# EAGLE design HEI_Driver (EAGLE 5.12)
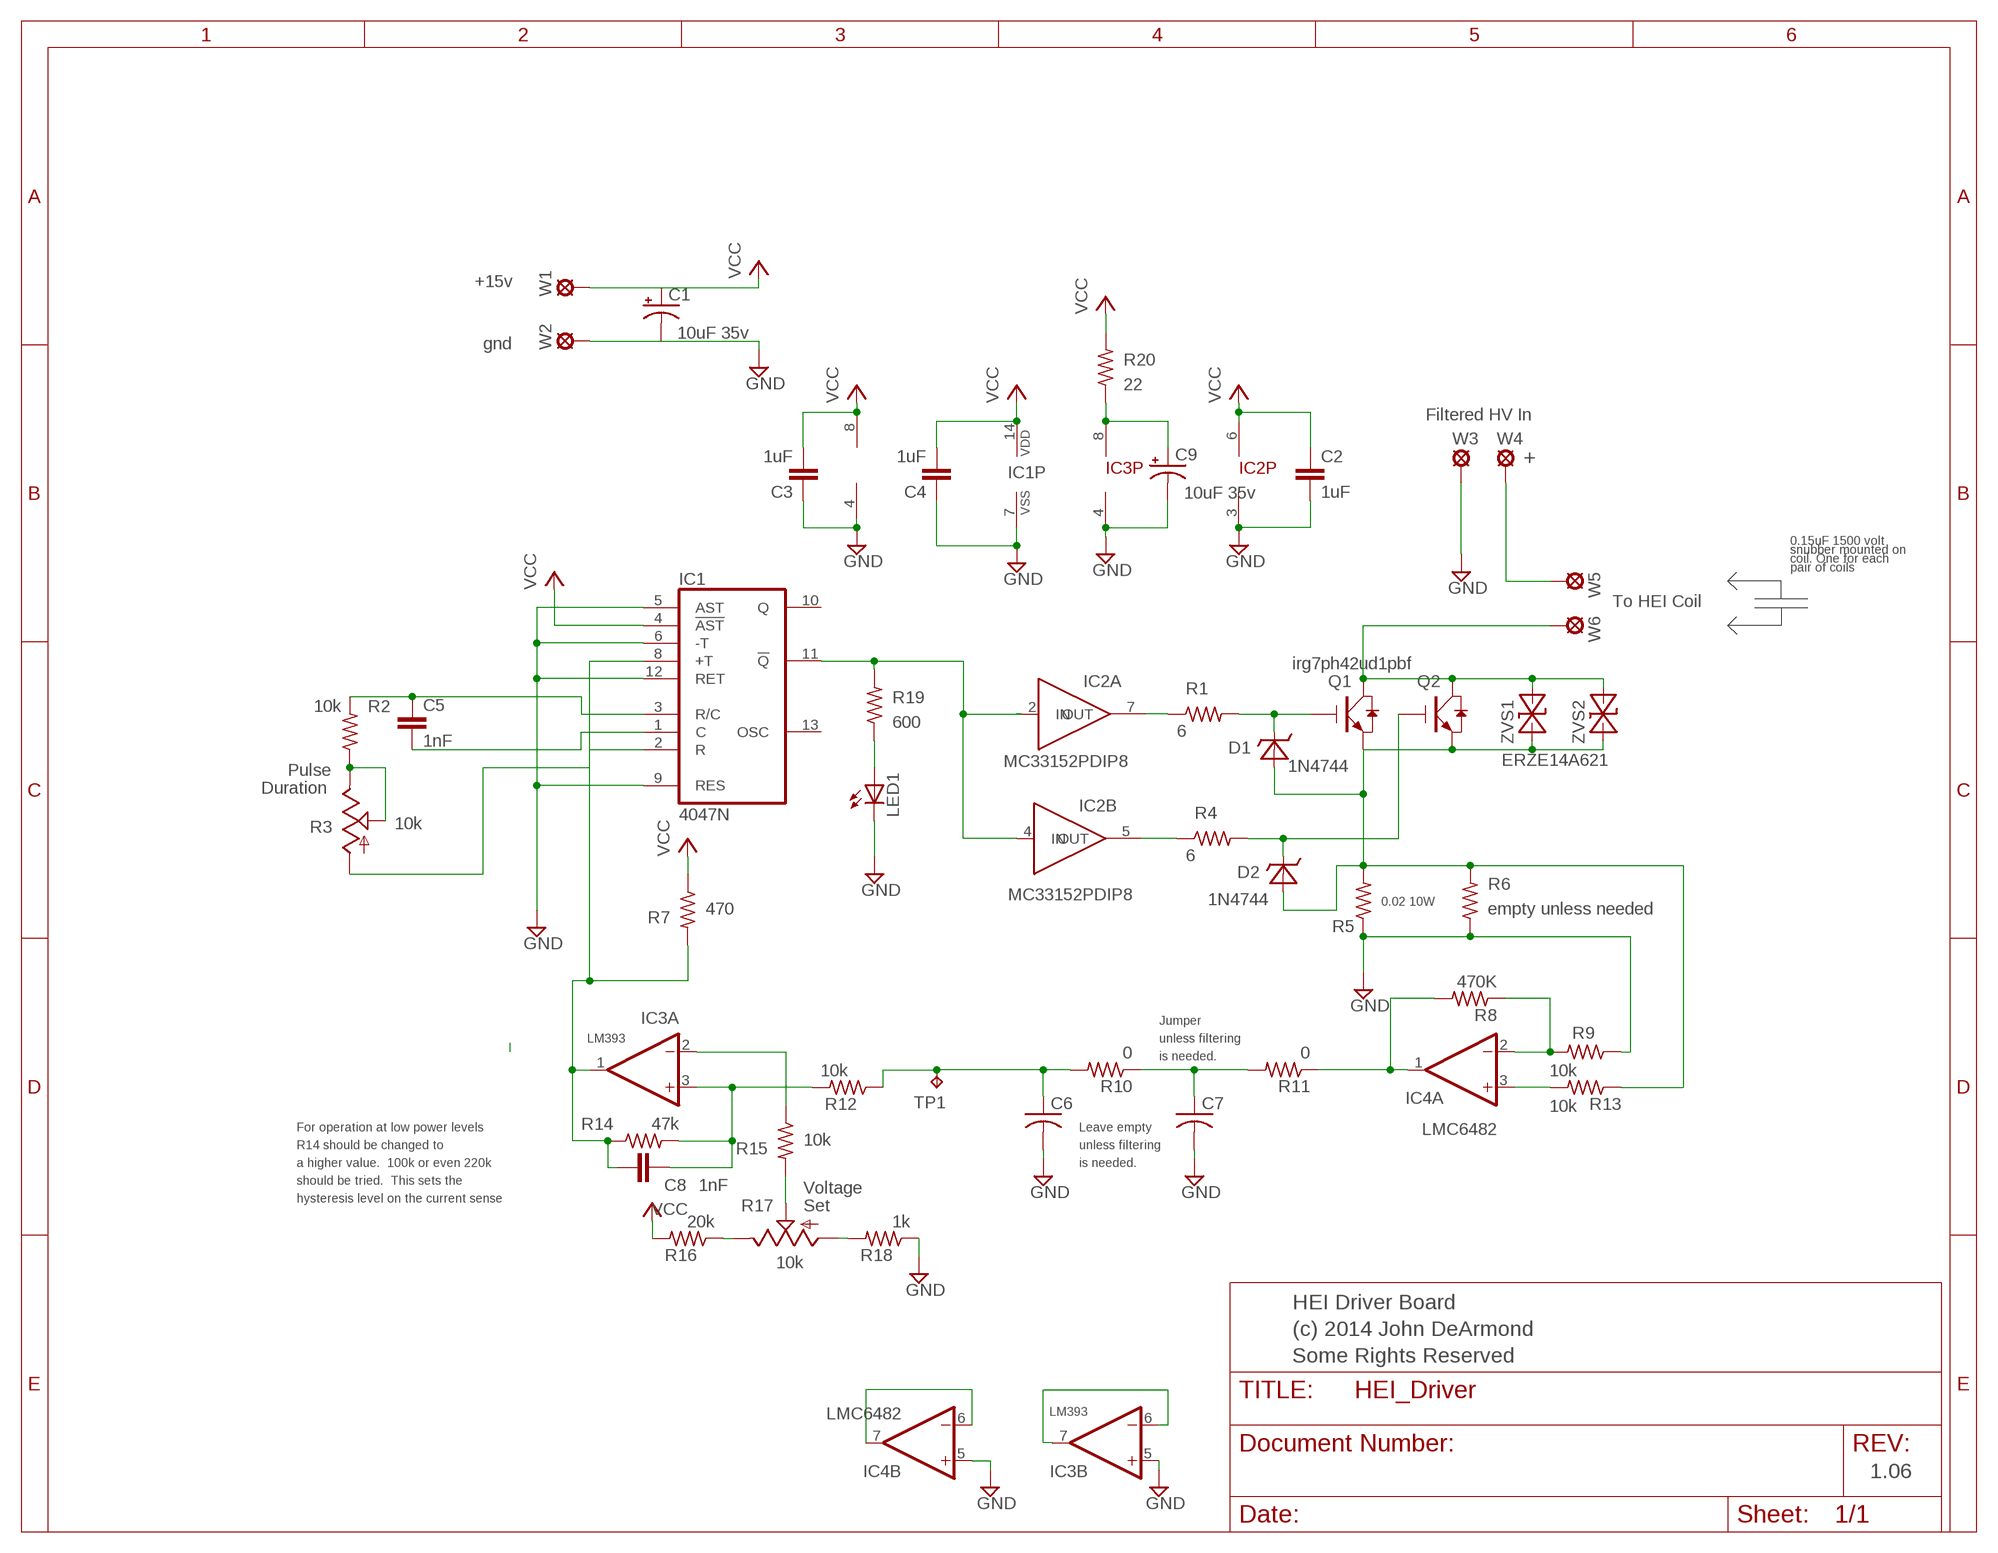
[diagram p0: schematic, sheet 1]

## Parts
C1  10uF 35v  CPOL-USE2.5-6  [E2,5-6]
C2  1uF  C5/5.5  [C5B5.5]
C3  1uF  C5/5.5  [C5B5.5]
C4  1uF  C5/5.5  [C5B5.5]
C5  1nF  C5/5.5  [C5B5.5]
C6  100p  C-US050-030X075  [C050-030X075]
C7  100p  C-US050-030X075  [C050-030X075]
C8  1nF  C5/5.5  [C5B5.5]
C9  10uF 35v  CPOL-USE2.5-6  [E2,5-6]
D1  1N4744  [DO41-10]
D2  1N4744  [DO41-10]
IC1  4047N  [DIL14]
IC2  MC33152PDIP8  [DIL08]
IC3  LM393  2AMP_P8+4N  [DIL08]
IC4  LMC6482  2AMP_P8+4D  [SO08]
LED1  LED_5MM_ROUND5MM_ROUND  [LED_5MM_ROUND]
Q1  irg7ph42udpbf  IGBT_DIODE  [TO247BV]
Q2  irg7ph42ud1pbf  IGBT_DIODE  [TO247BV]
R1  6  R-US_0207/10  [0207/10]
R2  10k  R-US_0207/10  [0207/10]
R3  10k  TRIM_US-  [3_TENTH_INCH_PADS]
R4  6  R-US_0207/10  [0207/10]
R5  0.02 10W  R-US_0613/15  [P0613/15-0.065_DRILL]
R6  empty unless needed  R-US_0613/15  [P0613/15-0.065_DRILL]
R7  470  R-US_0207/10  [0207/10]
R8  470K  R-US_0207/10  [0207/10]
R9  10k  R-US_0207/10  [0207/10]
R10  0  R-US_0207/10  [0207/10]
R11  0  R-US_0207/10  [0207/10]
R12  10k  R-US_0207/10  [0207/10]
R13  10k  R-US_0207/10  [0207/10]
R14  47k  R-US_0207/10  [0207/10]
R15  10k  R-US_0207/10  [0207/10]
R16  20k  R-US_0207/10  [0207/10]
R17  10k  TRIM_US-  [3_TENTH_INCH_PADS]
R18  1k  R-US_0207/10  [0207/10]
R19  600  R-US_0207/10  [0207/10]
R20  22  R-US_0207/10  [0207/10]
TP1  TPPAD1-17  [P1-17]
W1  PAD_25  [PAD_2.5MM]
W2  PAD_25  [PAD_2.5MM]
W3  PAD_25  [PAD_2.5MM]
W4  PAD_25  [PAD_2.5MM]
W5  PAD_25  [PAD_2.5MM]
W6  PAD_25  [PAD_2.5MM]
ZVS1  ERZE14A621  TVSTVS_0.45  [TVS_0.45]
ZVS2  ZNR14621  TVSTVS_0.45  [TVS_0.45]

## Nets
CURRENT_SENSE_+: D1.A D2.A Q1.S(E) Q2.S(E) R5.2 R6.2 R13.1 ZVS1.P$1(A1) ZVS2.P$1(A1)
GND: C1.- C2.2 C3.1 C4.1 C6.2 C7.2 C9.- IC1.5(AST) IC1.6(-T) IC1.7(VSS) IC1.9(RES) IC1.12(RET) IC2.3(P:-PWR) IC3.4(P:-PWR) IC3.5(B:+IN) IC4.4(P:V-) IC4.5(B:+IN) LED1.P$2(C) R5.1 R6.1 R9.1 R18.1 W2.W$1(MP) W3.W$1(MP)
MAIN_CURRENT: C6.1 R10.2 R12.1 TP1.TP
N$1: D1.C Q1.G R1.2
N$2: IC2.7(A:OUT) R1.1
N$3 [High Voltage]: Q1.D(C) Q2.D(C) W6.W$1(MP)
N$4: IC4.3(A:+IN) R13.2
N$5 [High Voltage]: W4.W$1(MP) W5.W$1(MP)
N$6: IC1.11(!Q) IC2.2(A:IN) IC2.4(B:IN) R19.2
N$7: IC2.5(B:OUT) R4.1
N$8: IC3.6(B:-IN) IC3.7(B:OUT)
N$9: C8.2 IC3.3(A:+IN) R12.2 R14.2
N$10: IC4.2(A:-IN) R8.1 R9.2
N$11: R15.2 R17.2(S)
N$12: C5.1 IC1.3(R/C) R2.2
N$14: C8.1 IC1.8(+T) IC3.1(A:OUT) R7.2 R14.1
N$15: R16.1 R17.3(E)
N$16: R17.1(A) R18.2
N$17: C5.2 IC1.1(C)
N$18: IC1.2(R) R3.1(A)
N$19: R2.1 R3.2(S) R3.3(E)
N$20: IC3.2(A:-IN) R15.1
N$21: IC4.1(A:OUT) R8.2 R11.1
N$22: D2.C Q2.G R4.2
N$23: LED1.P$1(A) R19.1
N$24: C9.+ IC3.8(P:PWR) R20.1
N$55: C7.1 R10.1 R11.2
N$66: IC4.6(B:-IN) IC4.7(B:OUT)
VCC: C1.+ C2.1 C3.2 C4.2 IC1.4(!AST) IC1.14(VDD) IC2.6(P:PWR) IC4.8(P:V+) R7.1 R16.2 R20.2 W1.W$1(MP)
Unconnected: IC1.10(Q) IC1.13(OSC) ZVS1.P$2(A2) ZVS2.P$2(A2)

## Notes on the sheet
- +15v
- gnd
- Filtered HV In
- +
- 0.15uF 1500 volt
- snubber mounted on
- coil. One for each
- pair of coils
- To HEI Coil
- Pulse
- Duration
- Jumper
- unless filtering
- is needed.
- For operation at low power levels | Leave empty
- R14 should be changed to | unless filtering
- a higher value.  100k or even 220k | is needed.
- should be tried.  This sets the
- Voltage
- hysteresis level on the current sense
- Set
- HEI Driver Board
- (c) 2014 John DeArmond
- Some Rights Reserved
- 1.06

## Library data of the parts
C1 C9 = rcl:CPOL-US: POLARIZED CAPACITOR, American symbol
C2-C5 C8 = capacitor-wima:C: CAPACITOR
C6 C7 = 00John:C-US: CAPACITOR, American symbol
D1 D2 = 00John:1N4744: 1N4744 15 volt 1 watt Zener Diode
IC1 = 00John:4047: LP monostable/astable MULTIVIBRATOR
IC2 = 00John:MC33152: MC33152 High Speed Dual non-Inverting Mosfet Gate Driver. 1.5 amp Totem Pole output
IC3 = 00John:2AMP_P8+4: OP AMP
IC4 = linear:2AMP_P8+4: OP AMP
LED1 = 00John:LED_5MM_ROUND: LED, Single
Q1 Q2 = 00John:IGBT_DIODE: IGBT with reverse diode
R1 R4-R6 R8-R11 R13 R19 R20 = 00John:R-US_: RESISTOR, American symbol
R2 R7 R12 R14-R16 R18 = rcl:R-US_: RESISTOR, American symbol
R3 R17 = 00John:TRIM_US-: POTENTIOMETER
TP1 = testpad:TP: Test pad
W1-W6 = 00John:PAD_25: Wire Pad
ZVS1 ZVS2 = 00John:TVS: Transient Voltage Suppressor

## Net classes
1 High Voltage: clearance 1.016 mm

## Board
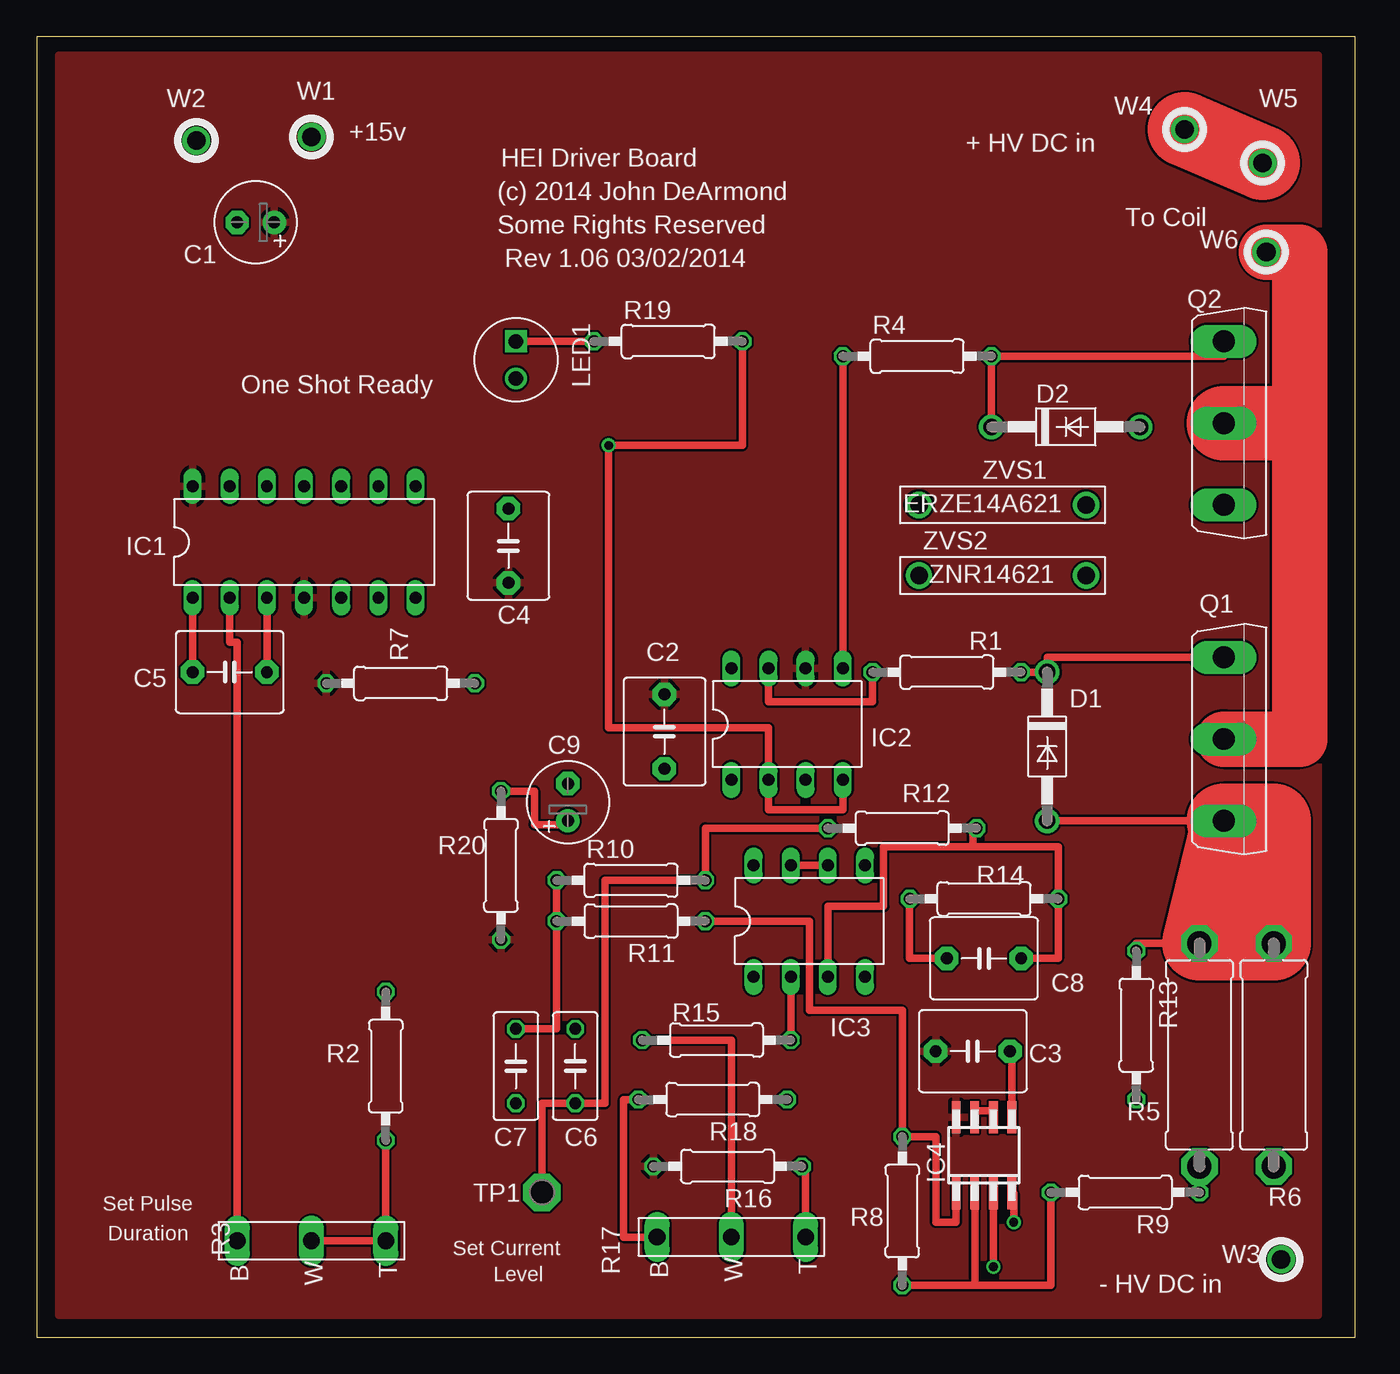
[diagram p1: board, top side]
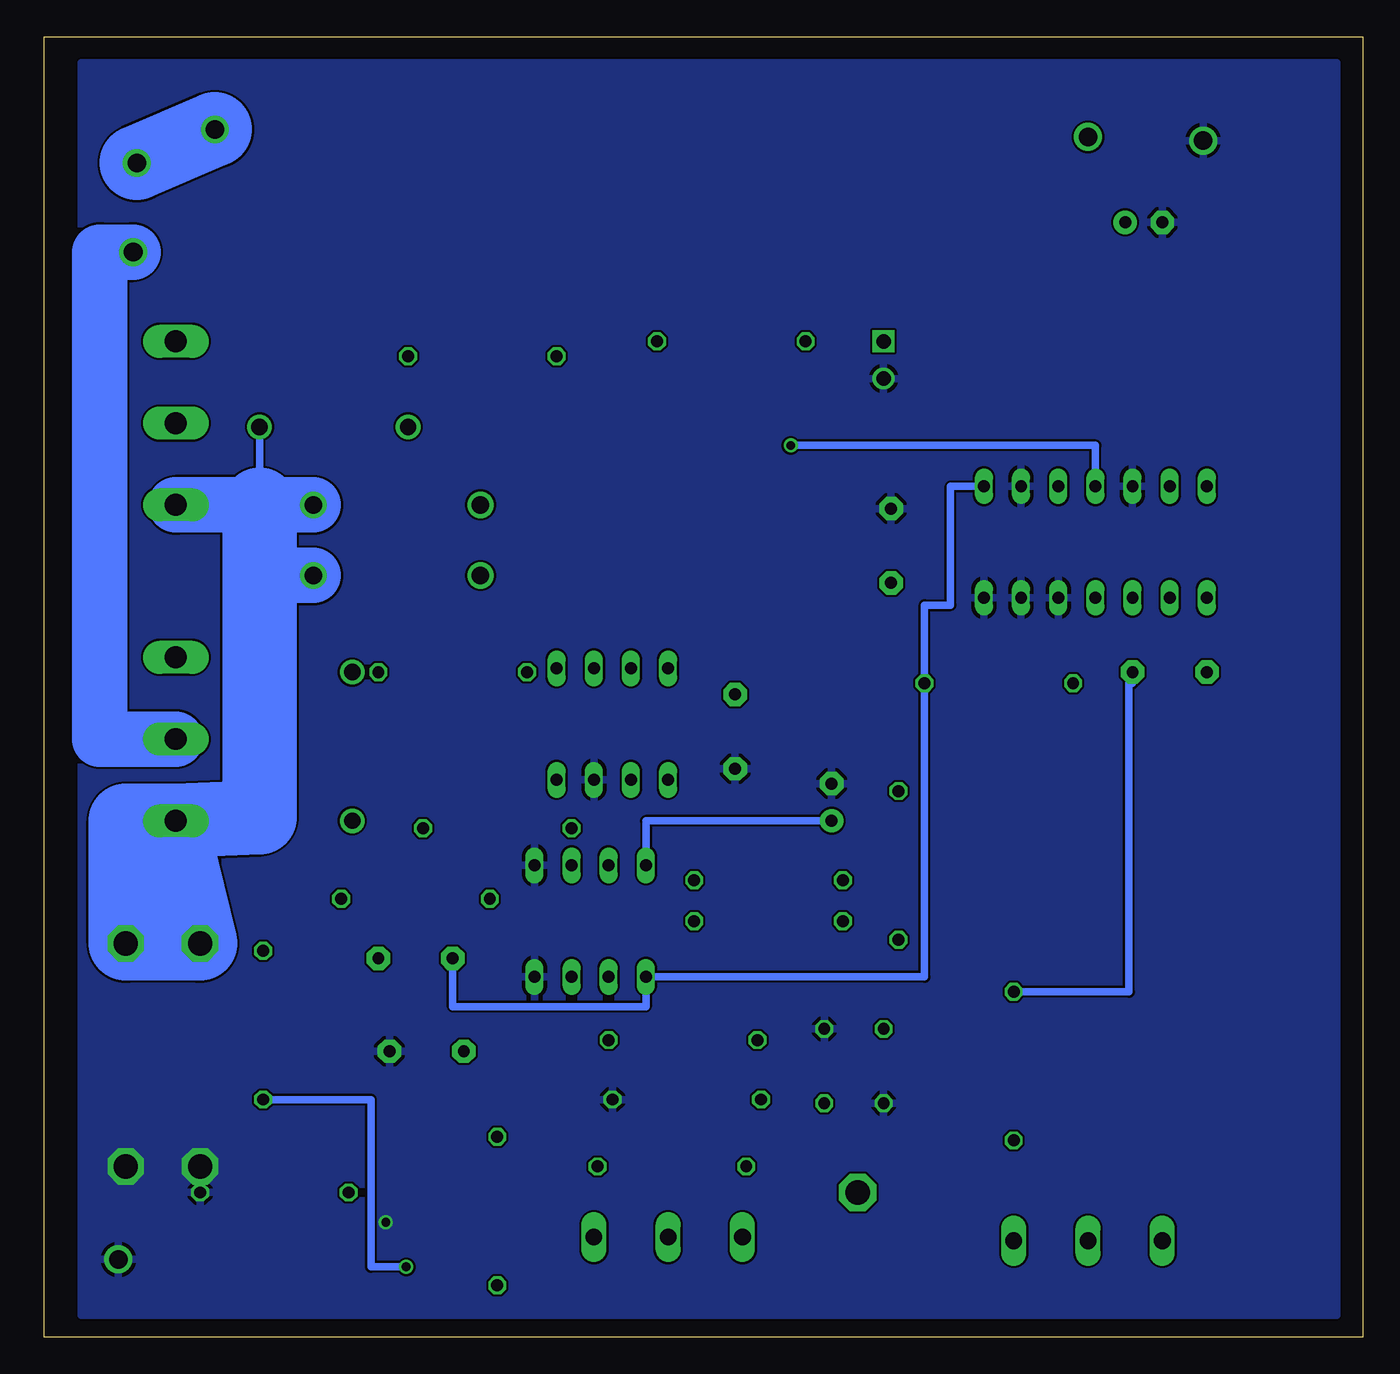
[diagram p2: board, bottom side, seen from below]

Size 90.17 x 88.9 mm. Coordinates in mm from the lower left corner, seen from the top.
Outline: 0,0 90.17,0 90.17,88.9 0,88.9 0,0
Copper layers (1*16): Top 0.0356mm / dielectric 1.5011mm / Bottom 0.0356mm
Design rules "OSH_Park_LaenPCBOrder": minimum track width 6mil, minimum drill 13mil, track to track 6mil, track to pad 6mil, pad to pad 6mil, via to via 6mil, smd to smd 6mil, copper to edge 15mil, drill to drill 6mil, minimum pad ring 7mil, minimum via ring 7mil, stop-mask expansion 3mil, vias tented up to drill 0mil, thermal gap 10mil

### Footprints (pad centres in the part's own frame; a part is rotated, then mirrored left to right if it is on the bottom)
E2,5-6 = drill 0.813 pad 1.6 round: + -1.27,0 | drill 0.813 pad 1.6 octagon: - 1.27,0
C5B5.5 = drill 0.813 pad 1.6 octagon: 1 -2.54,0; 2 2.54,0
C050-030X075 = drill 0.813 octagon: 1 -2.54,0; 2 2.54,0
DO41-10 = drill 1.118 round: A 5.08,0; C -5.08,0
DIL14 = drill 0.813 long: 1 -7.62,-3.81; 2 -5.08,-3.81; 3 -2.54,-3.81; 4 0,-3.81; 5 2.54,-3.81; 6 5.08,-3.81; 7 7.62,-3.81; 8 7.62,3.81; 9 5.08,3.81; 10 2.54,3.81; 11 0,3.81; 12 -2.54,3.81; 13 -5.08,3.81; 14 -7.62,3.81
DIL08 = drill 0.813 long: 1 -3.81,-3.81; 2 -1.27,-3.81; 3 1.27,-3.81; 4 3.81,-3.81; 5 3.81,3.81; 6 1.27,3.81; 7 -1.27,3.81; 8 -3.81,3.81
SO08 = smd 0.6 x 2.2: 1 -1.905,-2.6; 2 -0.635,-2.6; 3 0.635,-2.6; 4 1.905,-2.6; 5 1.905,2.6; 6 0.635,2.6; 7 -0.635,2.6; 8 -1.905,2.6
LED_5MM_ROUND = drill 1 square: P$1 0,0 | drill 1 round: P$2 2.54,0
TO247BV = drill 1.499 long: D 0,-2.921; G -5.588,-2.921; S 5.588,-2.921
0207/10 = drill 0.813 octagon: 1 -5.08,0; 2 5.08,0
3_TENTH_INCH_PADS = drill 1.143 long: 1 0,5.08; 2 0,0; 3 0,-5.08
P0613/15-0.065_DRILL = drill 1.651 octagon: 1 -7.62,0; 2 7.62,0
P1-17 = drill 1.702 pad 2.54 octagon: TP 0,0
PAD_2.5MM = drill 1.27 round: W$1 0,0
TVS_0.45 = drill 1.2 round: P$1 -5.715,0; P$2 5.715,0

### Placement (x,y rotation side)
C1  14.99,76.2 180 top
C2  42.93,41.4 270 top
C3  64.01,19.56 180 top
C4  32.26,54.1 270 top
C5  13.21,45.47 180 top
C6  36.83,18.54 90 top
C7  32.77,18.54 270 top
C8  64.77,25.91 0 top
C9  36.32,36.58 90 top
D1  69.09,40.39 270 top
D2  70.36,62.23 0 top
IC1  18.29,54.36 0 top
IC2  51.31,41.91 0 top
IC3  52.83,28.45 0 top
IC4  64.77,12.45 0 top
LED1  32.77,68.07 270 top
Q1  84.07,40.89 270 top
Q2  84.07,62.48 270 top
R1  62.23,45.47 0 top
R2  23.88,18.54 90 top
R3  18.8,6.6 90 top
R4  60.2,67.06 0 top
R5  79.5,19.3 90 top
R6  84.58,19.3 90 top
R7  24.89,44.7 0 top
R8  59.18,8.64 90 top
R9  74.42,9.91 180 top
R10  40.64,31.24 0 top
R11  40.64,28.45 180 top
R12  59.18,34.8 0 top
R13  75.18,21.34 270 top
R14  64.77,29.97 0 top
R15  46.48,20.32 180 top
R16  47.24,11.68 180 top
R17  47.5,6.86 90 top
R18  46.23,16.26 180 top
R19  43.18,68.07 0 top
R20  31.75,32.26 270 top
TP1  34.54,9.91 0 top
W1  18.8,82.04 0 top
W2  10.92,81.79 0 top
W3  85.09,5.33 0 top
W4  78.49,82.55 0 top
W5  83.82,80.26 0 top
W6  84.07,74.17 0 top
ZVS1  66.04,56.9 180 top
ZVS2  66.04,52.07 180 top

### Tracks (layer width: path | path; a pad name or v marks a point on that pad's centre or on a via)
CURRENT_SENSE_+
  Top 0.508: Q1.S D1.A | R13.1 75.18,26.92 R5.2
  Top 5.08: Q1.S 81.53,35.31 R5.2 R6.2 84.58,35.31 81.79,35.31
  Bottom 0.508: 75.44,56.9 D2.A
  Bottom 3.81: Q2.S 75.44,56.9 ZVS1.P$1 | ZVS2.P$1 74.68,52.07 75.44,52.83
  Bottom 5.08: 81.79,35.31 84.58,35.31 R6.2 R5.2 81.53,35.31 Q1.S 75.44,35.56 75.44,52.83 75.44,56.9
GND  (via drill 0.6)
  Top 0.508: IC4.5 66.67,19.56 C3.1 | IC4.4 66.8,9.85 v66.8,7.87
  pour Bottom: 1.78,1.52 87.63,1.52 87.63,87.12 1.78,87.12
MAIN_CURRENT
  Top 0.508: R12.1 45.72,34.8 R10.2 38.86,31.24 38.86,16 C6.1 34.54,16 TP1.TP
N$1
  Top 0.508: Q1.G 69.09,46.48 D1.C R1.2
N$2
  Top 0.508: IC2.7 50.04,43.43 57.15,43.43 R1.1
N$3
  Top 3.81: Q1.D 86.36,40.89 86.36,62.48 | 86.36,62.48 86.36,74.17 W6.W$1 | 86.36,62.48 85.6,62.48
  Top 5.08: 85.6,62.48 Q2.D
  Bottom 3.81: Q1.D 86.36,40.89 86.36,74.17 W6.W$1
N$4  (via drill 0.6)
  Top 0.508: v65.41,4.83 IC4.3
  Bottom 0.508: R13.2 67.82,16.26 67.82,4.83 v65.41,4.83
N$5
  Top 5.08: W4.W$1 W5.W$1
  Bottom 5.08: W4.W$1 W5.W$1
N$6  (via drill 0.6)
  Top 0.508: IC2.4 55.12,36.07 50.04,36.07 IC2.2 50.04,41.66 39.12,41.66 v39.12,60.96 48.26,60.96 R19.2
  Bottom 0.508: IC1.11 18.29,60.96 v39.12,60.96
N$7
  Top 0.508: IC2.5 R4.1
N$8
  Top 0.508: IC3.7 IC3.6
N$9
  Top 0.508: 68.58,25.91 C8.2 69.85,25.91 R14.2 69.85,33.53 64.01,33.53 | IC3.3 54.1,29.46 57.91,29.46 57.91,33.53 64.01,33.53 | R12.2 64.01,34.8 64.01,33.53
N$10
  Top 0.508: R9.2 69.34,3.56 64.14,3.56 | 64.14,3.56 IC4.2 | R8.1 64.14,3.56
N$11
  Top 0.508: R17.2 47.5,20.32 R15.2
N$12
  Top 0.508: C5.1 IC1.3
  Bottom 0.508: R2.2 16,23.62 16,44.7 15.75,44.7 C5.1
N$14
  Top 0.508: C8.1 59.69,25.91 R14.1
  Bottom 0.508: IC1.8 28.19,58.17 28.19,50.04 29.97,50.04 R7.2 29.97,24.64 IC3.1 49.02,22.61 62.23,22.61 C8.1
N$15
  Top 0.508: R17.3 52.58,11.68 R16.1
N$16
  Top 0.508: R18.2 40.13,16.26 40.13,6.86 R17.1
N$17
  Top 0.508: C5.2 IC1.1
N$18
  Top 0.508: R3.1 13.72,47.5 13.21,47.5 IC1.2
N$19
  Top 0.508: R2.1 R3.3 R3.2
N$20
  Top 0.508: R15.1 IC3.2
N$21
  Top 0.508: IC4.1 62.87,7.87 61.47,7.87 61.47,13.72 R8.2 59.18,22.35 52.83,22.35 52.83,28.45 R11.1
N$22
  Top 0.508: Q2.G 81.15,67.06 R4.2 D2.C
N$23
  Top 0.508: LED1.P$1 R19.1
N$24
  Top 0.508: R20.1 34.04,37.34 34.04,35.05 36.32,35.05 C9.+
  Bottom 0.508: C9.+ 49.02,35.31 IC3.8
N$55
  Top 0.508: R10.1 R11.2 35.56,21.08 C7.1
N$66
  Top 0.508: IC4.7 64.14,15.49 65.41,15.49 IC4.6
VCC
  pour Top: 1.52,1.52 87.63,1.52 87.63,87.63 1.52,87.63

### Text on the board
tPlace: +15v | + HV DC in | HEI Driver Board | (c) 2014 John DeArmond | To Coil | Some Rights Reserved | Rev 1.06 03/02/2014 | One Shot Ready | Set Pulse | Duration | Set Current | Level | - HV DC in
